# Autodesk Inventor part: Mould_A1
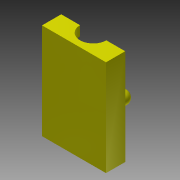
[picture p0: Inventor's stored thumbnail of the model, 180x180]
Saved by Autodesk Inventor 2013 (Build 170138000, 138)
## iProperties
Created: 2013-06
Part Number: Mould_A1
Material: Generic
Document SubType Name: Modeling
Designer: frankenteddy
Density: 1 g/cm^3
Author: frankenteddy
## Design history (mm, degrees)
sketch "Sketch1"
  geometry: L1 (-10, 12)-(10, 12); L2 (10, 12)-(10, -12); L3 (10, -12)-(-10, -12); L4 (-10, -12)-(-10, 12); L5 (-10, 12)-(-10, 15); L6 (-10, 15)-(10, 15); L7 (10, 15)-(10, 12); 3 further points
  constraints: 14 end point, 3 parallel, 2 midpoint, 2 perpendicular, 1 collinear, 1 horizontal, 1 horizontal alignment, 1 vertical alignment
  dimensions: "d0" = 24 distance of L1.end L2.end; "d2" = 20 distance of L1.start L1.end; "d65" = 3 distance of L1.start L5.end
extrude "Extrusion1" new body sketch "Sketch1" distance "d3" = 6; taper "d4" = 0 deg
workplane "Work Plane1"
sketch "Sketch2"
  geometry: L1 (-10, -12)-(10, -12) reference; L2 (5, 12)-(5, 6.138); L3 (0, 12)-(5, 12); L4 (2, 2.265)-(2, 0); L5 (2, 0)-(0, 0); L6 (0, 0)-(0, 12); A1 r 2 centre (4, 2.265) between (3.5, 4.202) and (2, 2.265); A2 r 2 centre (3, 6.138) between (3.5, 4.202) and (5, 6.138); 3 further points
  constraints: 10 end point, 4 point on circle, 3 perpendicular, 3 tangent, 2 centre point, 2 vertical alignment, 1 horizontal, 1 parallel
  dimensions: "d15" = 2 radius of A1; "d18" = 2 radius of A2; "d55" = 5 distance of L3.start L2.start; "d56" = 2 distance between parallel lines of L6 L4; "d59" = 12 distance between parallel lines of L5 L3
revolve "Revolution1" sketch "Sketch2" stored, may be unused: angle "d20" = 90 deg
mirror "Mirror1"
workplane "Work Plane2"
sketch "Sketch3"
  geometry: L1 (-17.279, 0)-(16.833, 0) reference; L2 (0, 16.632)-(0, -16.118) reference; L3 (17.279, 0)-(-16.833, 0); L4 (-1, 9)-(-3, 9); L5 (-3, 9)-(-3, 8); L6 (-3, 8)-(-1, 8); L7 (-1, 8)-(-1, 9); C1 r 2 at (-7, 0); C2 r 2.2 at (7, 0); 1 further point
  constraints: 14 end point, 3 horizontal, 2 centre point, 2 parallel, 2 perpendicular, 2 symmetric about line, 1 vertical
  dimensions: "d24" = 4 diameter of C1; "d26" = 0 vertical distance of point (0, 0) C1.centre; "d27" = 7 distance of point (0, 0) C1.centre; "d36" = 4.4 diameter of C2; "d37" = 7 distance from line of L2 C2.centre; "d38" = 0 distance from line of L1 C2.centre; "d47" = 2 distance of L6.end L5.end; "d48" = 1 distance of L5.end L4.end; "d49" = 1 distance between parallel lines of L2 L7; "d50" = 8 distance between parallel lines of L1 L6
extrude "Extrusion6" join sketch "Sketch3" distance "d60" = 4; taper "d61" = 0 deg
extrude "Extrusion7" cut sketch "Sketch3" distance "d62" = 4; taper "d63" = 0 deg
fillet "Fillet3" dims "d64" = 2
extrude "Extrusion8" join sketch "Sketch1" distance "d66" = 6; taper "d67" = 0 deg
workplane "Work Plane3"
sketch "Sketch5"
  geometry: L1 (0, 15)-(4.1, 15); L2 (4.1, 15)-(4.1, 12); L3 (4.1, 12)-(0, 12); L4 (0, 12)-(0, 15); 1 further point
  constraints: 8 end point, 2 parallel, 1 horizontal, 1 perpendicular
  dimensions: "d71" = 4.1 distance of L2.end L3.end; "d72" = 3 distance of L1.end L2.end; "d73" = 12 distance from line of L3 point (0, 0)
revolve "Revolution4" sketch "Sketch5" stored, may be unused: angle "d74" = 90 deg
mirror "Mirror3"
body "Solid1"
other parameters: "d5" = 6, "d23" = 6, "d70" = 6
